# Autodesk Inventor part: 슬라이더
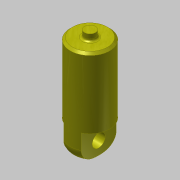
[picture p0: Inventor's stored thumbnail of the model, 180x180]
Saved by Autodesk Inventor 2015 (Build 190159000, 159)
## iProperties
Created: 2016-08
Part Number: 슬라이더
Material: 강철, 탄소
Document SubType Name: Modeling
Designer: mduedu
Density: 7.87 g/cm^3
Appearance: 노란색
Author: mduedu
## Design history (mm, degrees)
sketch "스케치1"
  geometry: C1 r 9 at (0, 0); 1 further point
  constraints: 1 centre point, 1 coincident
  dimensions: "d0" = 18 diameter of C1
extrude "돌출1" new body sketch "스케치1" distance "d1" = 45; taper "d2" = 0 deg
fillet "모깎기1" dims "d21" = 6
sketch "스케치6"
  geometry: L1 (9, 6)-(9, 45) reference; L2 (-9, 6)-(-9, 45) reference; L3 (9, 45)-(-9, 45) reference; L4 (0, 45)-(0, 0); L5 (9, 13)-(4, 13); L6 (4, 13)-(4, 0); L7 (4, 0)-(9, 0); L8 (9, 0)-(9, 13); L9 (-9, 13)-(-4, 13); L10 (-4, 13)-(-4, 0); L11 (-4, 0)-(-9, 0); L12 (-9, 0)-(-9, 13)
  constraints: 18 end point, 4 symmetric about line, 2 parallel, 2 perpendicular, 1 horizontal, 1 horizontal alignment, 1 midpoint, 1 point on line
  dimensions: "d22" = 13 distance of L7.end L5.start; "d24" = 4 distance between parallel lines of L6 L4
extrude "돌출5" cut sketch "스케치6" stored distance "d25" = 8; taper "d26" = 0 deg
sketch "스케치8"
  geometry: C1 r 3 at (6, 0); 1 further point
  constraints: 1 centre point, 1 horizontal alignment
  dimensions: "d27" = 6 diameter of C1; "d28" = 6 distance of point (0, 0) C1.centre
extrude "돌출6" cut sketch "스케치8" stored distance "d29" = 8; taper "d30" = 0 deg
chamfer "모따기2" distance "d43" = 1; stored, may be unused: second distance "d44" = 2, angle "d45" = 30 deg
sketch "스케치9"
  geometry: C1 r 2.5 at (0, 0); 1 further point
  constraints: 1 centre point, 1 coincident
  dimensions: "d47" = 5 diameter of C1
extrude "돌출7" join sketch "스케치9" distance "d48" = 3; taper "d49" = 0 deg
fillet "모깎기2" dims "d50" = 1
node "솔리드1"
